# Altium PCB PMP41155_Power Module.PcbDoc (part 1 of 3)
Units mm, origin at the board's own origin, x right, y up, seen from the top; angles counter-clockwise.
Board outline 40.5 x 74.05 mm, 8 copper layers (Top Layer, Layer 1, Layer 2, Layer 3, Layer 4, Layer 5, Layer 6, Bottom Layer), stack 1.58 mm thick; 130 components, 51 nets, 407 pads, 560 vias.
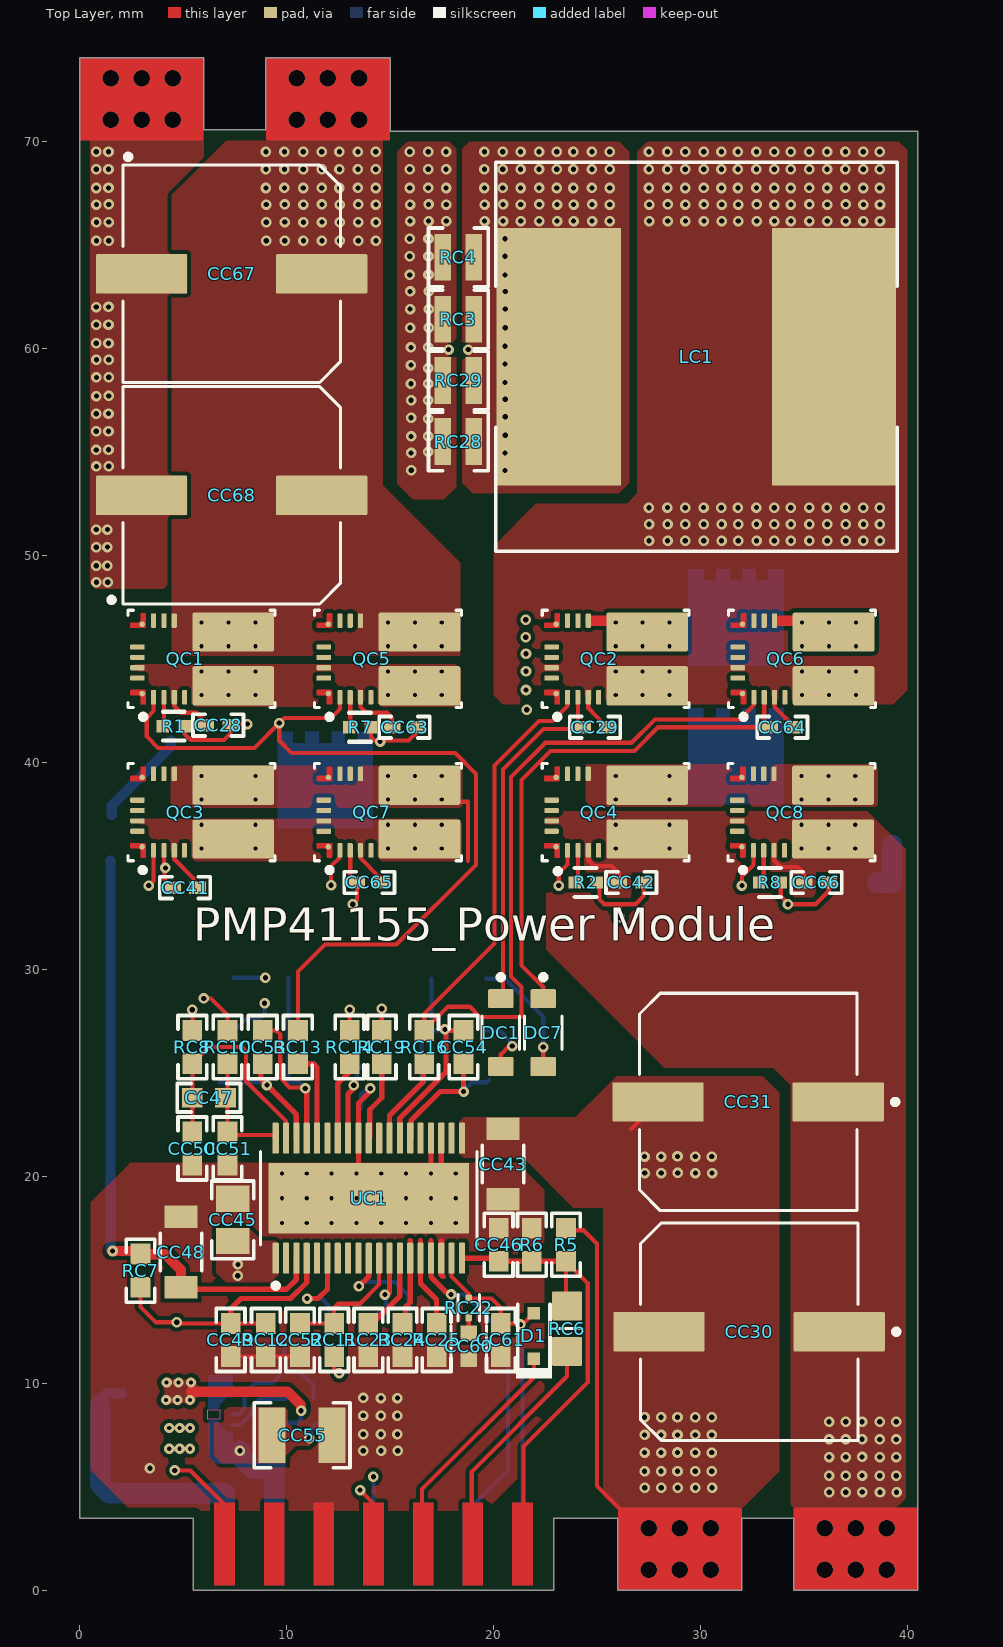
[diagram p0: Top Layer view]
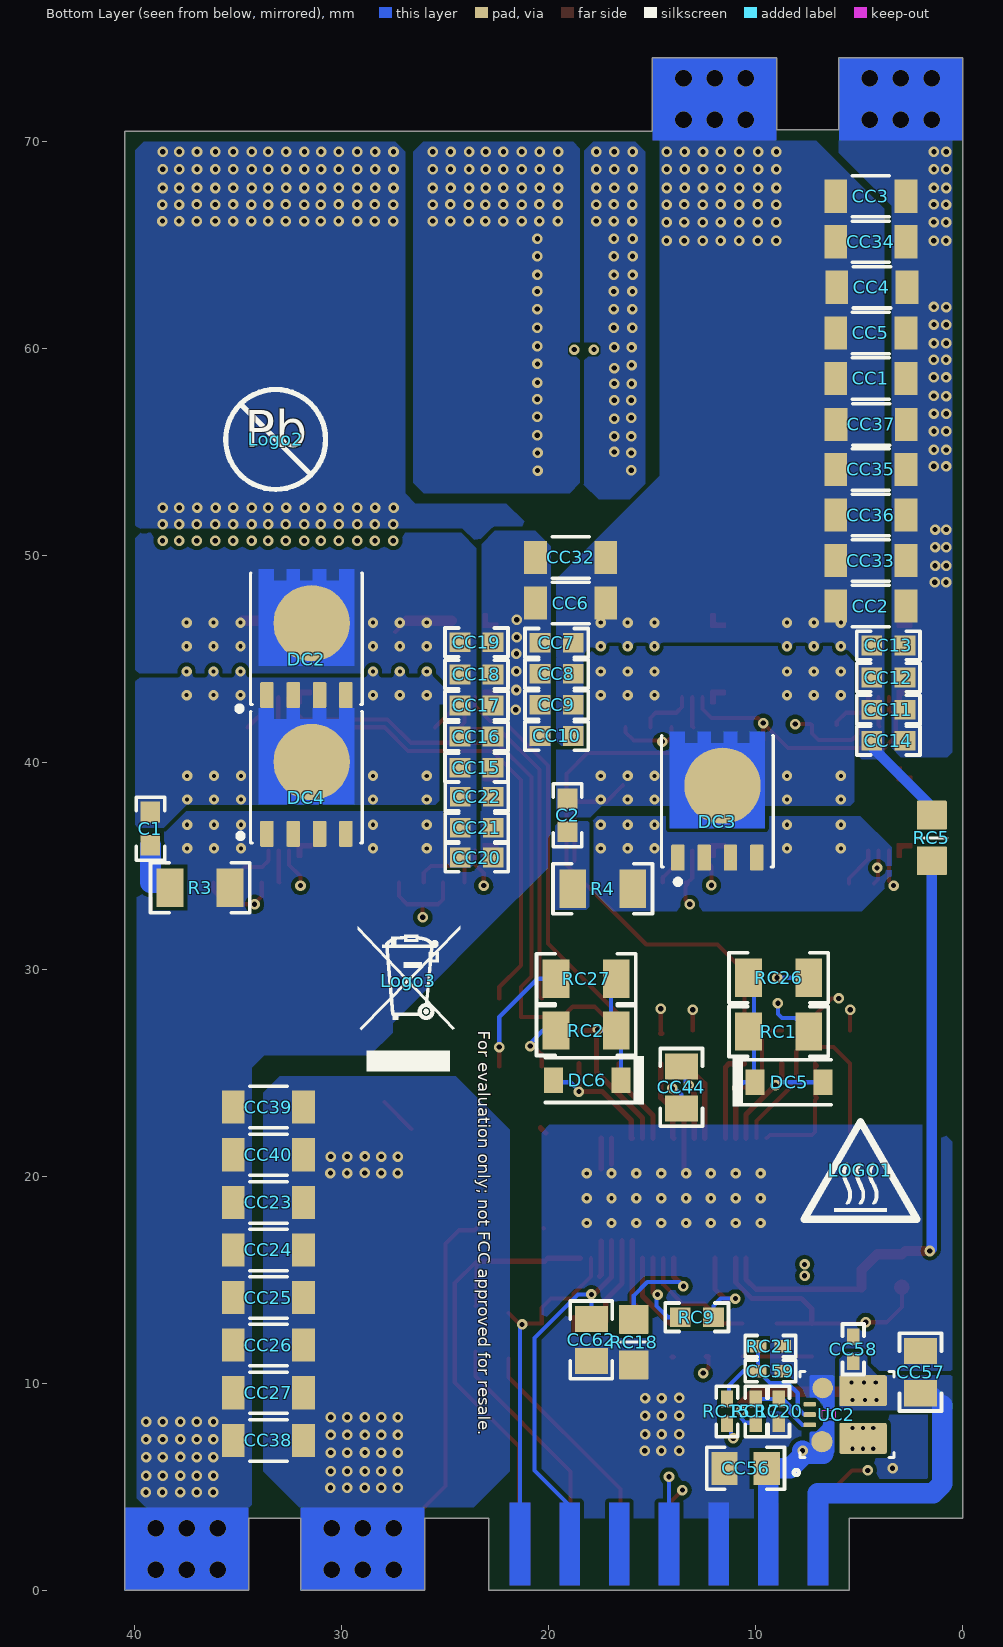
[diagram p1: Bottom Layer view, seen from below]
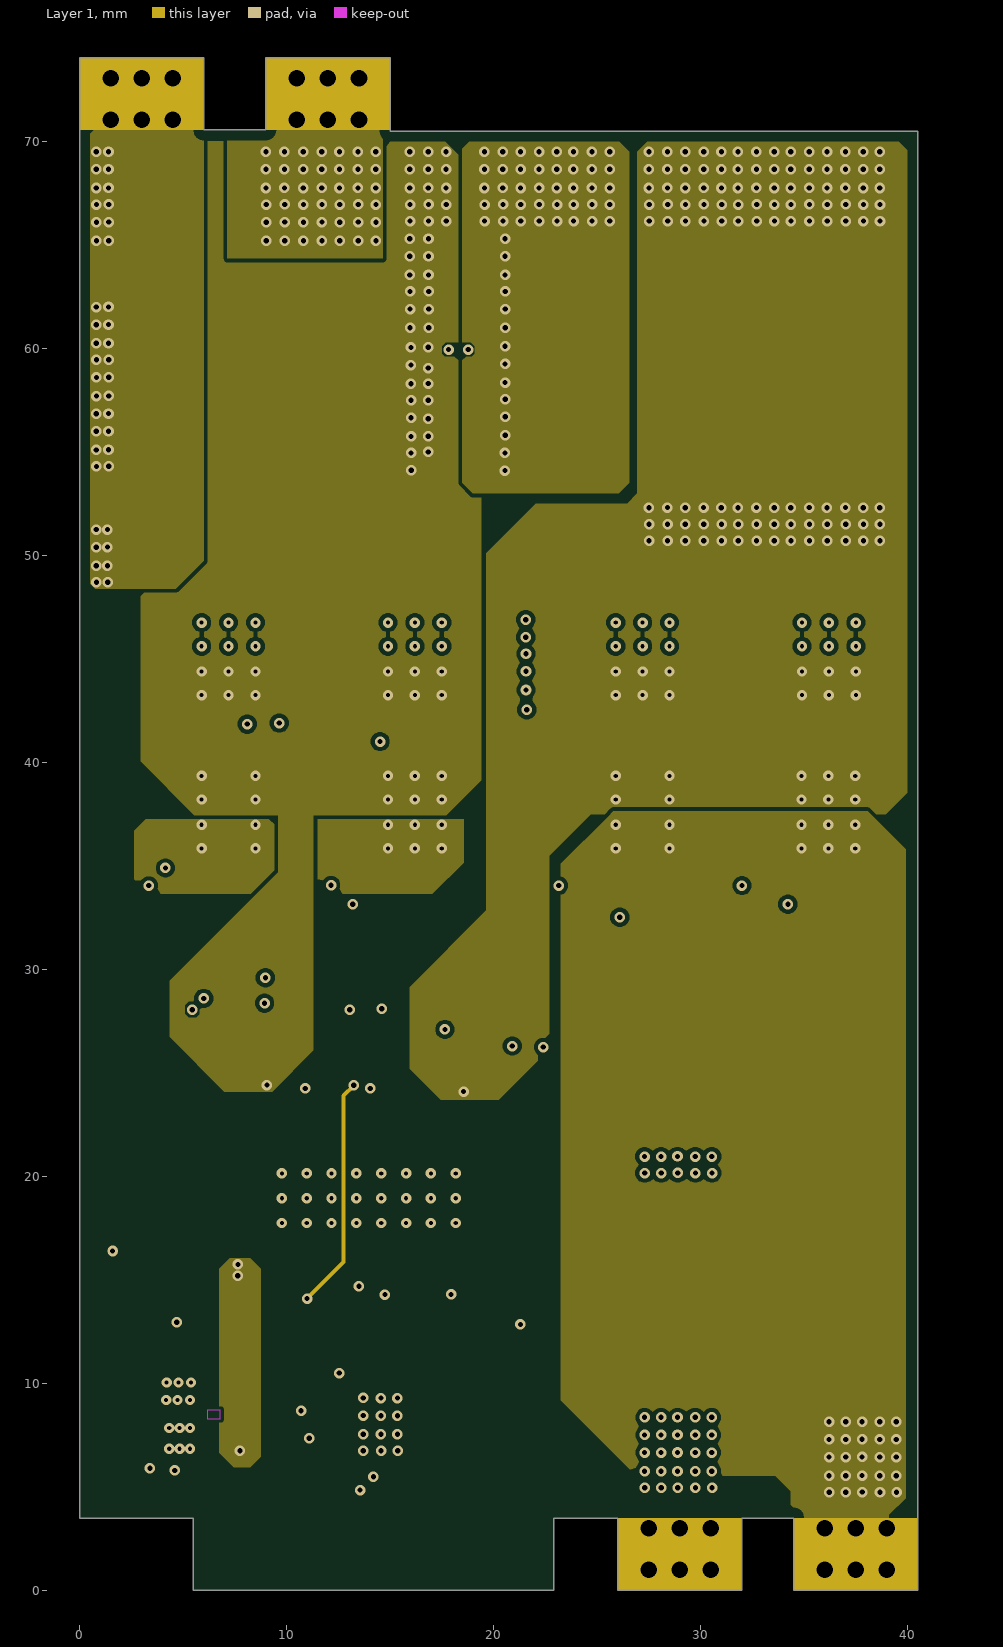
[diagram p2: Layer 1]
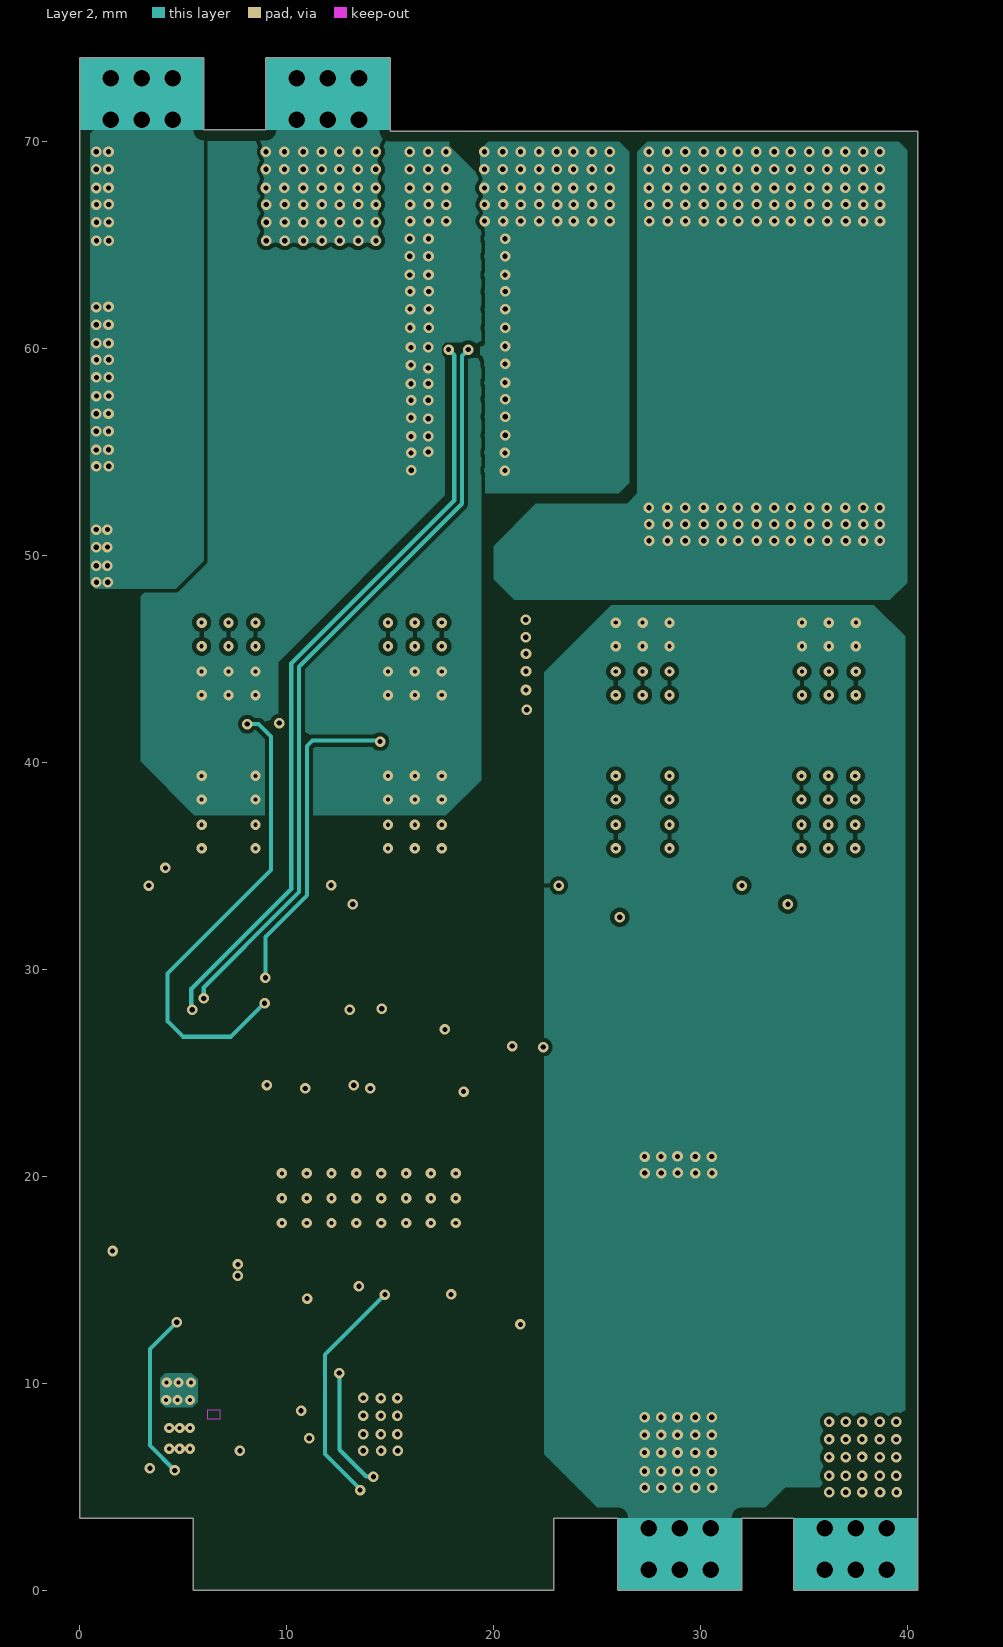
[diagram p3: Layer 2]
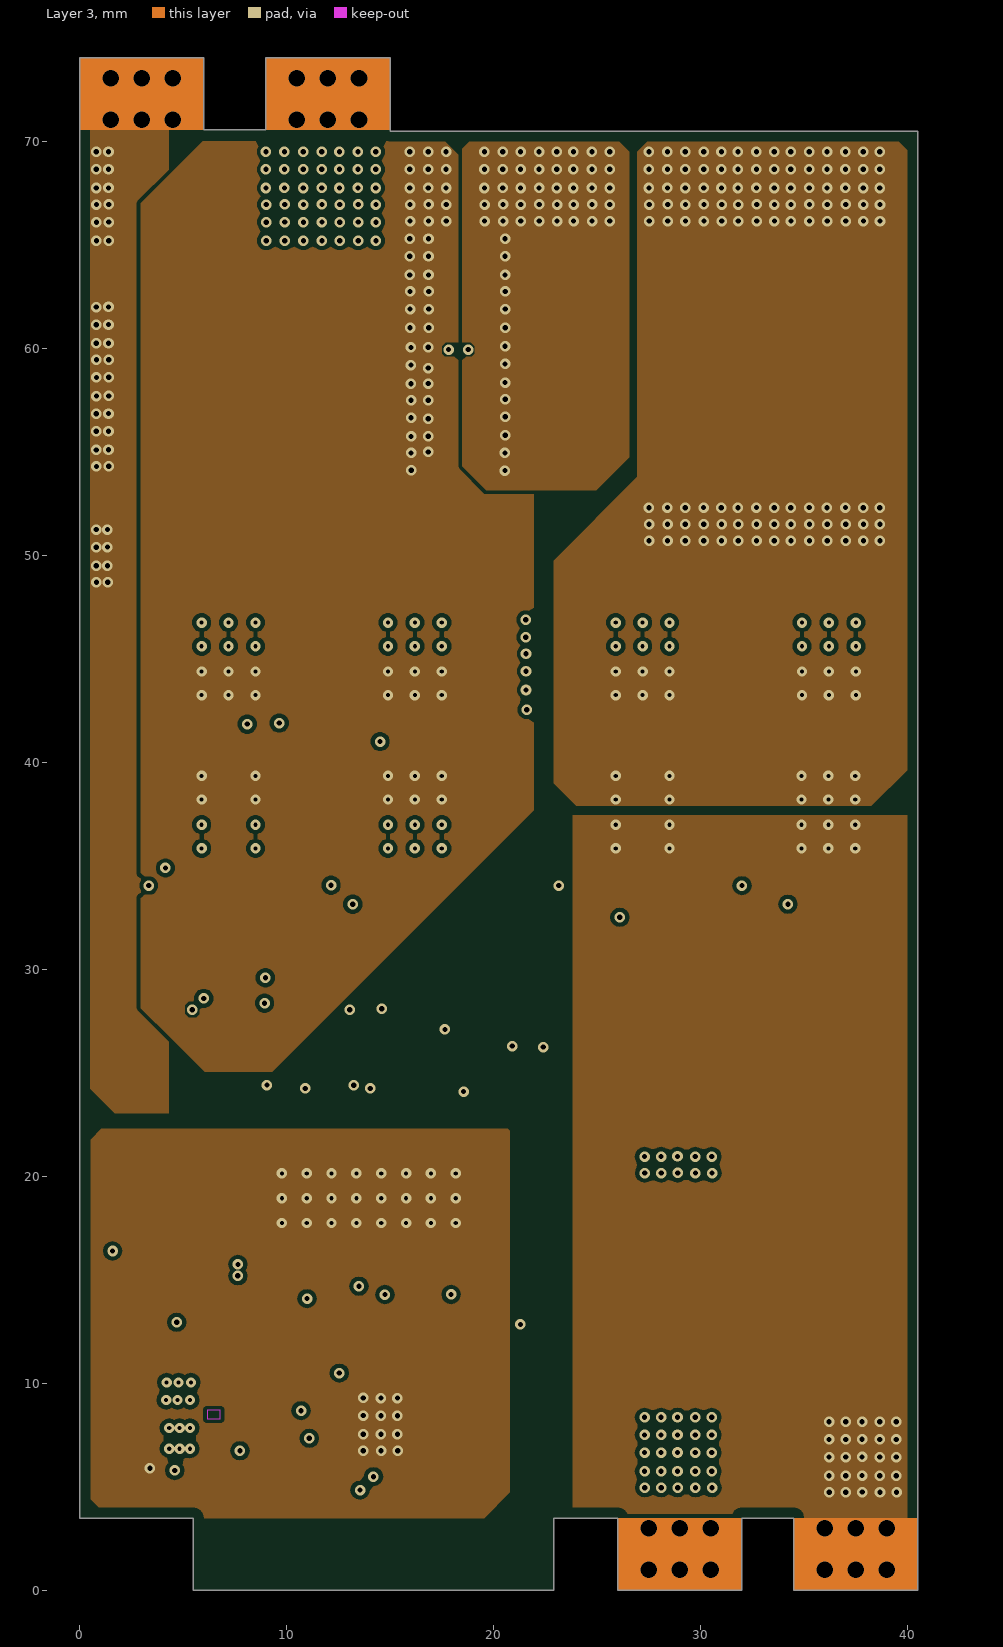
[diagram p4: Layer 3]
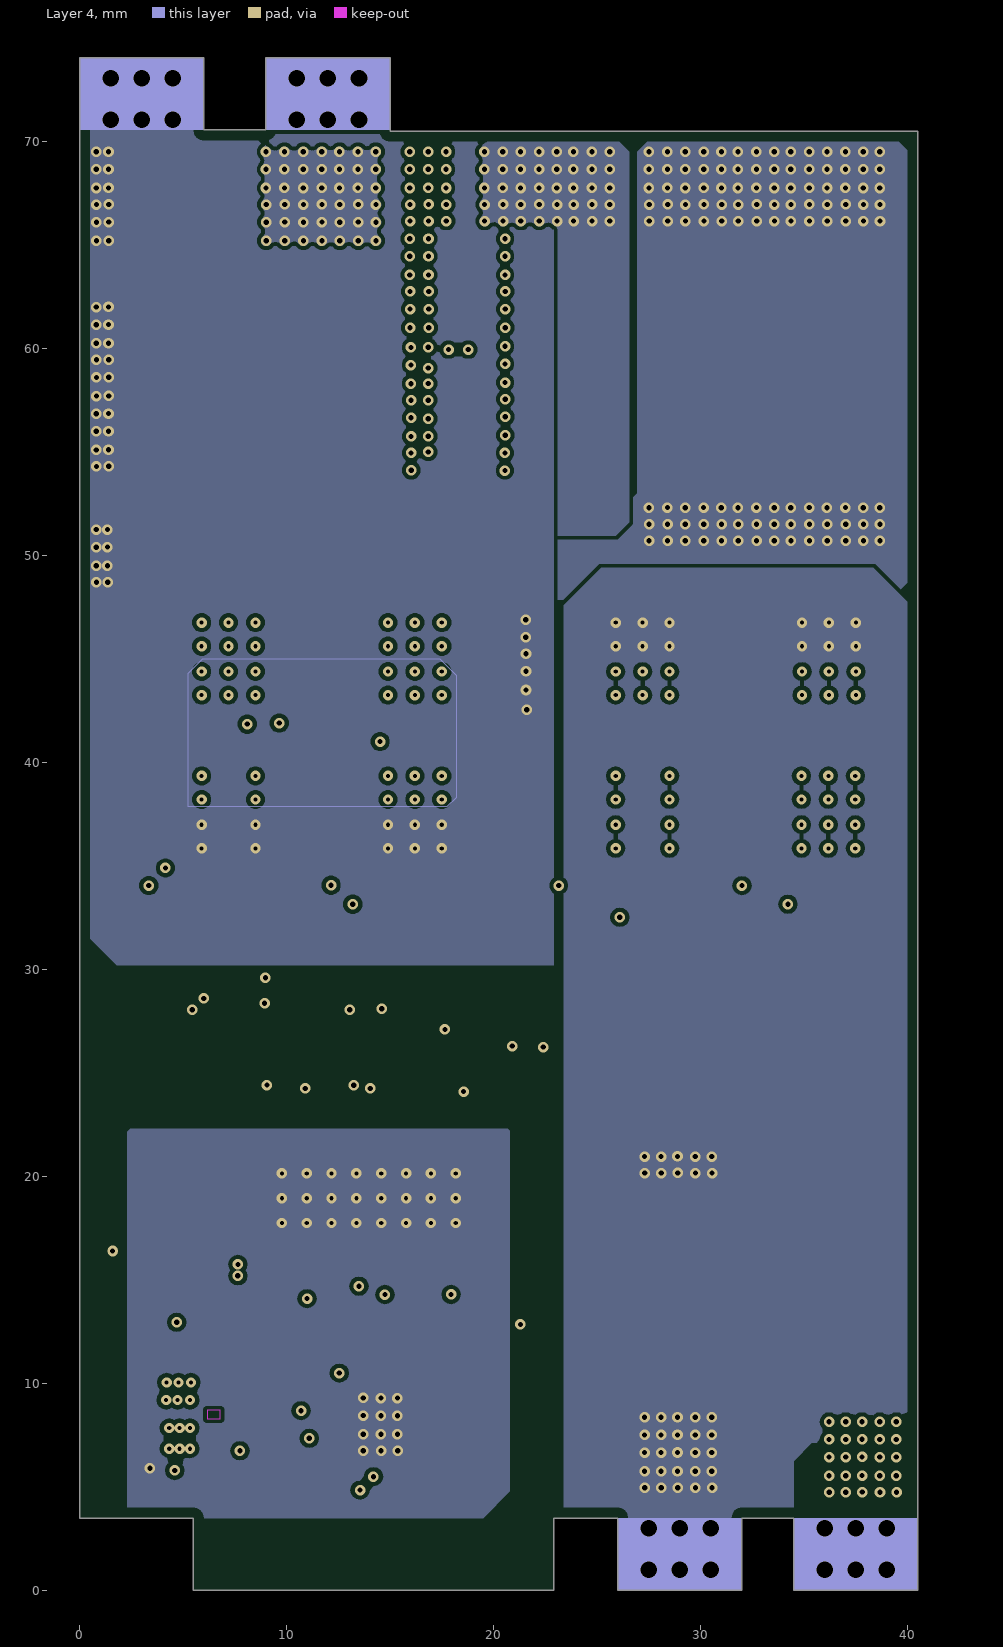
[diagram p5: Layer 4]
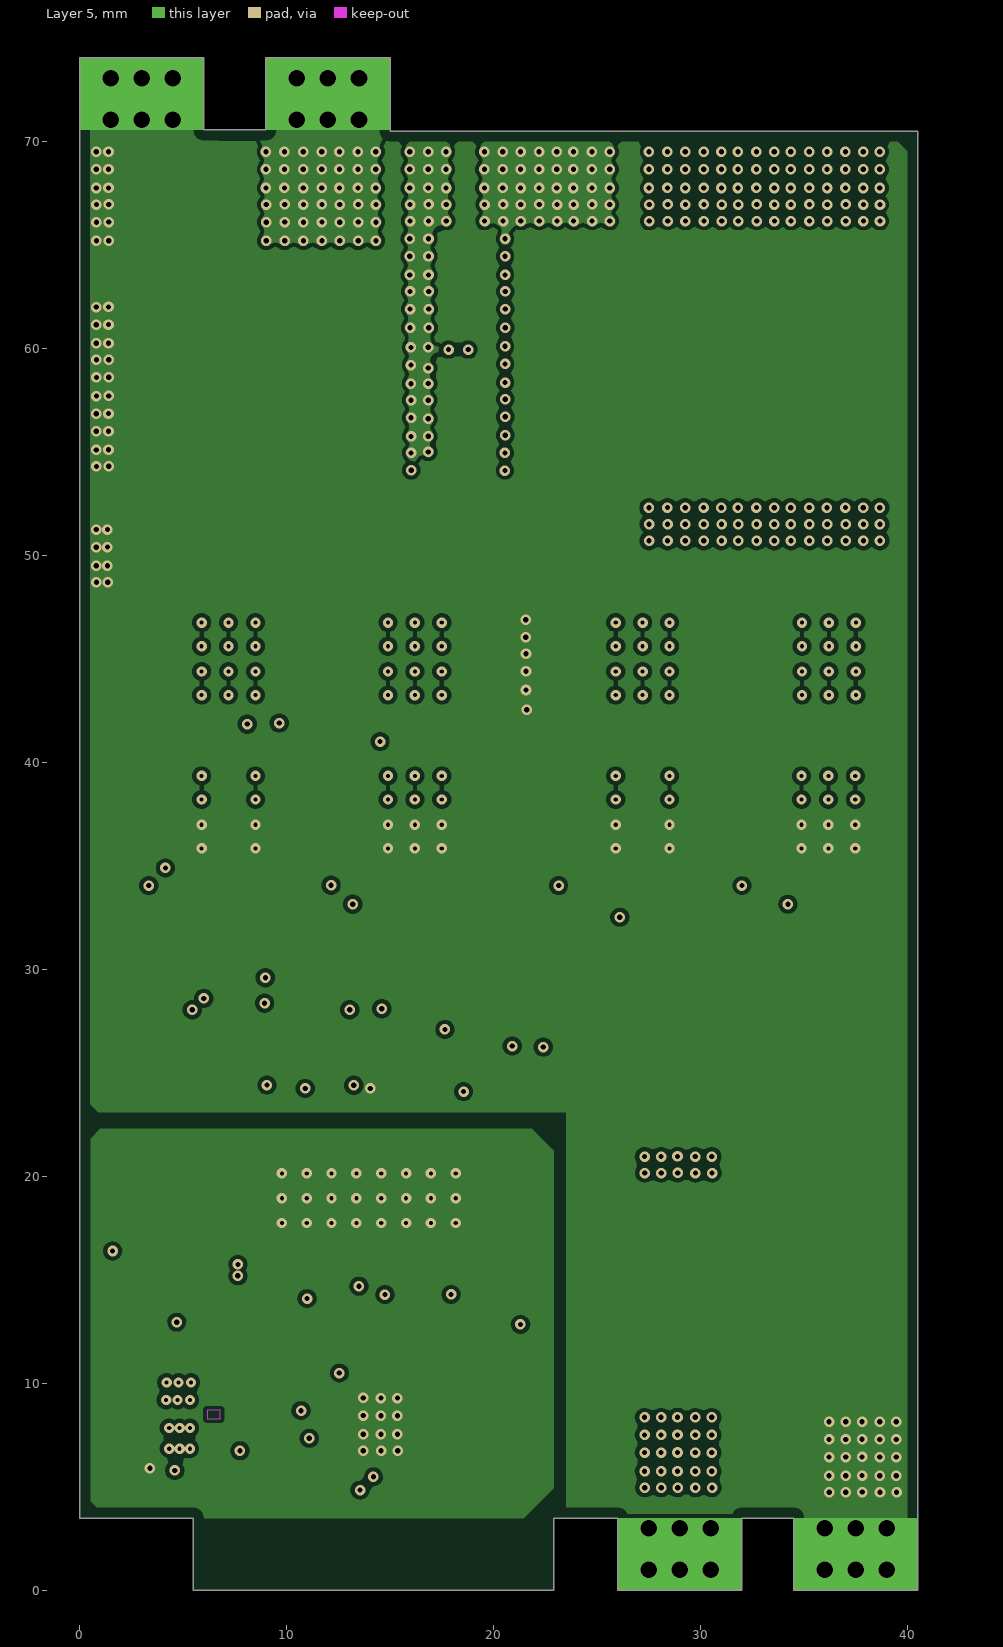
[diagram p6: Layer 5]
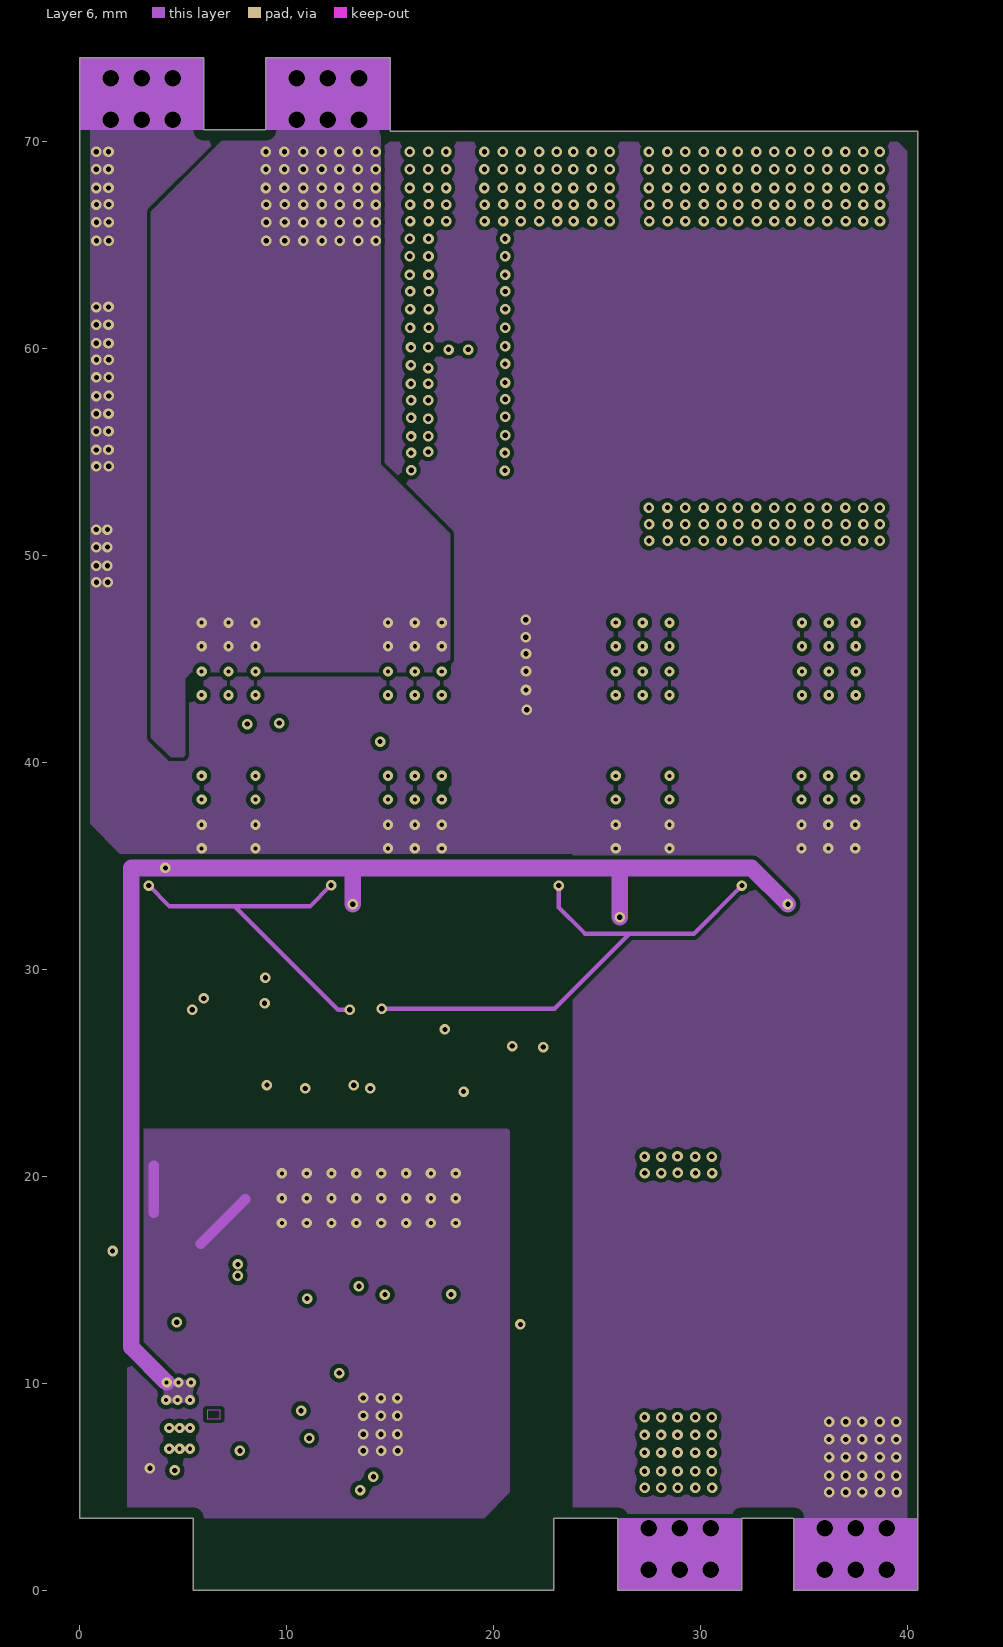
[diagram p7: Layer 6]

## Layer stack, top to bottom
Top Solder: solder mask 0.01, Solder Resist, Dk 3.5
Top Layer: signal copper 0.07
Dielectric 1: prepreg 0.26, FR-4, Dk 4.1
Layer 1: signal copper 0.07
Dielectric 2: core 0.1, FR-4, Dk 4.1
Layer 2: signal copper 0.07
Dielectric 3: core 0.1, FR-4, Dk 4.2
Layer 3: signal copper 0.07
Dielectric 4: core 0.1, FR-4, Dk 4.2
Layer 4: signal copper 0.07
Dielectric 5: core 0.1, FR-4, Dk 4.2
Layer 5: signal copper 0.07
Dielectric6: core 0.1, FR-4, Dk 4.6
Layer 6: signal copper 0.07
Dielectric 7: prepreg 0.26, FR-4, Dk 4.2
Bottom Layer: signal copper 0.07
Bottom Solder: solder mask 0.01, Solder Resist, Dk 3.5

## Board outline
5.5,0 5.5,3.5 0,3.5 0,74.05 6,74.05 6,70.55 9,70.55 9,74.05 15,74.05 15,70.5 40.5,70.5 40.5,0 34.5,0 34.5,3.5 32,3.5 32,0 26,0 26,3.5 22.9,3.5 22.9,0

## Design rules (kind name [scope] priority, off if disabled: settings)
AcuteAngle [All] p1: minimum=4.50000000000000E+0001 checktracksonly=FALSE
AssemblyTestPointUsage [All] p1: valid=2
BoardOutlineClearance BoardOutlineClearance_MountingHoles [OnCopper and InComponentClass('Mounting Holes')] p1: gap=1.016 ignorepadtopadclearanceinfootprint=FALSE
BoardOutlineClearance BoardOutlineClearance_Poly [OnCopper and IsPoly] p2: gap=0.508 ignorepadtopadclearanceinfootprint=FALSE
BoardOutlineClearance [OnCopper and Not InComponentClass('Logo') and not InComponentClass('FiducialMark') and not InRegion(1000,500,4000,800) and not InPoly] p3: gap=0.254 ignorepadtopadclearanceinfootprint=FALSE
Clearance Clearance_1 [InNetClass('HV') vs Not InNetClass('HV')] p1: gap=0.508 ignorepadtopadclearanceinfootprint=FALSE
Clearance Clearance_Keepouts [((IsTrack Or IsArc) And Not InPoly) And IsFree and IsKeepOut vs ((IsTrack Or IsArc) And Not InPoly) And IsFree and IsKeepOut] p2: gap=0 ignorepadtopadclearanceinfootprint=FALSE
Clearance Clearance_Poly [InPolygon] p3: gap=0.2 ignorepadtopadclearanceinfootprint=FALSE
Clearance Clearance_FiducialMark [IsKeepOut and InComponentClass('FiducialMark') vs IsPad and InComponentClass('FiducialMark')] p4: gap=0 ignorepadtopadclearanceinfootprint=FALSE
Clearance [All] p5: gap=0.178 ignorepadtopadclearanceinfootprint=FALSE except(0.1: Via-Via Via-Fill Via-Poly Via-Region Via-Text Via-Hole)
ComponentClearance ComponentClearance_MountingHoles_FiducialMarks [InComponentClass('Mounting Holes') vs InComponentClass('FiducialMark')] p1: gap=1.27 collisioncheckmode=3 verticalgap=0.254 showdistances=FALSE
ComponentClearance ComponentClearance_Shunt [InComponentClass('Header') vs InComponentClass('Shunt')] p2: gap=0 collisioncheckmode=3 verticalgap=0 showdistances=FALSE
ComponentClearance ComponentClearance_Logo [InComponentClass('Logo')] p3: gap=1.27 collisioncheckmode=3 verticalgap=0.254 showdistances=FALSE
ComponentClearance ComponentClearance_ScrewToNut [(HasFootprint('NY PMS 440 0025 PH')) vs (HasFootprint('Keystone_1902C'))] p4: gap=0.127 collisioncheckmode=3 verticalgap=0.254 showdistances=FALSE
ComponentClearance ComponentClearance_MountingHoles [InComponentClass('Mounting Holes')] p5: gap=6.35 collisioncheckmode=3 verticalgap=2540 showdistances=FALSE
ComponentClearance ComponentClearance_SmallPassives [HasFootprint('0201*') or HasFootprint('0402*') or HasFootprint('0508') or HasFootprint('0603*') or HasFootprint('0612') or HasFootprint('0805*') or HasFootprint('0815*') or HasFootprint('0830*') or HasFootprint('1206*') or HasFootprint('1210*') or HasFootprint('1808*') or HasFootprint('1812*') or HasFootprint('1825*') or HasFootprint('2010*') or HasFootprint('2220*') or HasFootprint('2225*') or HasFootprint('2512*') or HasFootprint('2728*') or HasFootprint('3518*') vs HasFootprint('0201*') or HasFootprint('0402*') or HasFootprint('0508') or HasFootprint('0603*') or HasFootprint('0612') or HasFootprint('0805*') or HasFootprint('0815*') or HasFootprint('0830*') or HasFootprint('1206*') or HasFootprint('1210*') or HasFootprint('1808*') or HasFootprint('1812*') or HasFootprint('1825*') or HasFootprint('2010*') or HasFootprint('2220*') or HasFootprint('2225*') or HasFootprint('2512*') or HasFootprint('2728*') or HasFootprint('3518*')] p6: gap=0.254 collisioncheckmode=3 verticalgap=0.254 showdistances=FALSE
ComponentClearance ComponentClearance_THtoSMT [IsThruComponent vs IsSMTComponent] p7: gap=1.016 collisioncheckmode=3 verticalgap=0.762 showdistances=FALSE
ComponentClearance ComponentClearance_THtoTH [IsThruComponent vs IsThruComponent] p8: gap=0.508 collisioncheckmode=3 verticalgap=0.508 showdistances=FALSE
ComponentClearance [All] p9: gap=0.254 collisioncheckmode=3 verticalgap=0.254 showdistances=FALSE
DiffPairsRouting [All] p1: maxlimit=2.54 minlimit=0.254 mostfreqgap=0.254 toplayer_minwidth=0.381 toplayer_maxwidth=0.381 toplayer_prefwidth=0.381 midlayer1_minwidth=0.381 midlayer1_maxwidth=0.381 midlayer1_prefwidth=0.381 midlayer2_minwidth=0.381 midlayer2_maxwidth=0.381 midlayer2_prefwidth=0.381 midlayer3_minwidth=0.381 midlayer3_maxwidth=0.381 midlayer3_prefwidth=0.381 midlayer4_minwidth=0.381 midlayer4_maxwidth=0.381 midlayer4_prefwidth=0.381 midlayer5_minwidth=0.381 midlayer5_maxwidth=0.381 midlayer5_prefwidth=0.381 midlayer6_minwidth=0.381 midlayer6_maxwidth=0.381 midlayer6_prefwidth=0.381 bottomlayer_minwidth=0.381 bottomlayer_maxwidth=0.381 bottomlayer_prefwidth=0.381 maxuncoupledlength=25.4
FabricationTestPointUsage TestPointUsage [All] p1: valid=2 allowmultiple=FALSE
FabricationTestpoint Testpoint [All] p1: side=3 testpointundercomponent=TRUE minsize=1.016 maxsize=2.54 preferedsize=1.524 minholesize=0 maxholesize=1.016 preferedholesize=0.813 testpointgrid=0.025 allowsidetop=TRUE allowsidebottom=TRUE usegrid=TRUE gridtolerance=0
FanoutControl Fanout_LCC [IsLCC] p1: bgadir=Out bgaviamode=Centered fanoutstyle=Auto fanoutdirection=Alternating viagrid=0.025 // Fanout_LCC (Default Rule)
FanoutControl Fanout_BGA [IsBGA] p2: bgadir=Out bgaviamode=Centered fanoutstyle=Auto fanoutdirection=Alternating viagrid=0.025 // Fanout_BGA (Default Rule)
FanoutControl Fanout_Default [All] p4: bgadir=Out bgaviamode=Centered fanoutstyle=Auto fanoutdirection=Alternating viagrid=0.025 // Fanout_Default (Default Rule)
FanoutControl Fanout_Small [(CompPinCount < 5)] p5: bgadir=Out bgaviamode=Centered fanoutstyle=Auto fanoutdirection=OutThenIn viagrid=0.025 // Fanout_Small (Default Rule)
HoleSize [All] p1: absolutevalues=TRUE maxlimit=6.375 minlimit=0.2 maxpercent=80.000 minpercent=20.000
MinimumAnnularRing MinimumAnnularRing_ThermalPadVias [IsVia and InAnyComponent] p1: minimumring=0.15
MinimumAnnularRing [All] p2: minimumring=0.127
MinimumSolderMaskSliver MinimumSolderMaskSliver_Logo [InComponentClass('Logo') vs InComponentClass('Logo')] p1: minsoldermaskwidth=0.018
MinimumSolderMaskSliver [All] p2: minsoldermaskwidth=0.1
PlaneConnect [All] p1: planeconnectstyle=Direct reliefexpansion=0.254 reliefentries=4 reliefconductorwidth=0.254 reliefairgap=0.254
PolygonConnect PolygonConnect_19 [All vs IsNamedPolygon('SGND') Or  IsNamedPolygon('SGND') Or  IsNamedPolygon('SGND') Or  IsNamedPolygon('SW2') Or  IsNamedPolygon('VBAT_DISCH_IN') Or  IsNamedPolygon('VBAT_DISCH_IN') Or  IsNamedPolygon('VBAT_DISCH_IN') Or  IsNamedPolygon('CSB_DISCH') Or  IsNamedPolygon('SGND') Or  IsNamedPolygon('no net') Or  IsNamedPolygon('SGND') Or  IsNamedPolygon('SNGD') Or  IsNamedPolygon('SGND') Or  IsNamedPolygon('SGND') Or  IsNamedPolygon('SW2') Or  IsNamedPolygon('SGND') Or  IsNamedPolygon('SGND') Or  IsNamedPolygon('CSA_DISCH') Or  IsNamedPolygon('48V_DISCH_OUT') Or  IsNamedPolygon('VBAT_DISCH_IN') Or  IsNamedPolygon('SGND') Or  IsNamedPolygon('SGND') Or  IsNamedPolygon('48V_DISCH_OUT') Or  IsNamedPolygon('SGND') Or  IsNamedPolygon('CSA_DISCH') Or  IsNamedPolygon('no net') Or  IsNamedPolygon('SGND') Or  IsNamedPolygon('SGND') Or  IsNamedPolygon('48V_DISCH_OUT') Or  IsNamedPolygon('48V_DISCH_OUT') Or  IsNamedPolygon('SGND') Or  IsNamedPolygon('12V_AUX') Or  IsNamedPolygon('48V_DISCH_OUT') Or  IsNamedPolygon('VBAT_DISCH_IN') Or  IsNamedPolygon('VBAT_DISCH_IN') Or  IsNamedPolygon('SGND')] p1: connectstyle=Direct reliefconductorwidth=0.254 reliefentries=4 polygonreliefangle="90 Angle" airgapwidth=0.254
PolygonConnect PolygonConnect_18 [All vs IsNamedPolygon('SW2') Or  IsNamedPolygon('VBAT_DISCH_IN') Or  IsNamedPolygon('VBAT_DISCH_IN') Or  IsNamedPolygon('VBAT_DISCH_IN') Or  IsNamedPolygon('48V_DISCH_OUT') Or  IsNamedPolygon('VBAT_DISCH_IN') Or  IsNamedPolygon('SGND') Or  IsNamedPolygon('SGND') Or  IsNamedPolygon('SGND') Or  IsNamedPolygon('SGND') Or  IsNamedPolygon('SGND') Or  IsNamedPolygon('VBAT_DISCH_IN') Or  IsNamedPolygon('SGND') Or  IsNamedPolygon('CSA_DISCH') Or  IsNamedPolygon('SGND') Or  IsNamedPolygon('48V_DISCH_OUT') Or  IsNamedPolygon('48V_DISCH_OUT') Or  IsNamedPolygon('no net') Or  IsNamedPolygon('SGND') Or  IsNamedPolygon('SGND') Or  IsNamedPolygon('SGND') Or  IsNamedPolygon('SGND') Or  IsNamedPolygon('12V_AUX') Or  IsNamedPolygon('CSA_DISCH') Or  IsNamedPolygon('CSB_DISCH') Or  IsNamedPolygon('SGND') Or  IsNamedPolygon('SGND') Or  IsNamedPolygon('VBAT_DISCH_IN')] p2: connectstyle=Direct reliefconductorwidth=0.254 reliefentries=4 polygonreliefangle="90 Angle" airgapwidth=0.254
PolygonConnect PolygonConnect_17 [All vs IsNamedPolygon('SGND') Or  IsNamedPolygon('VBAT_DISCH_IN') Or  IsNamedPolygon('SGND') Or  IsNamedPolygon('VBAT_DISCH_IN') Or  IsNamedPolygon('CSA_DISCH') Or  IsNamedPolygon('VBAT_DISCH_IN') Or  IsNamedPolygon('VBAT_DISCH_IN') Or  IsNamedPolygon('SGND') Or  IsNamedPolygon('SGND') Or  IsNamedPolygon('48V_DISCH_OUT') Or  IsNamedPolygon('CSA_DISCH') Or  IsNamedPolygon('SGND') Or  IsNamedPolygon('VBAT_DISCH_IN') Or  IsNamedPolygon('SGND') Or  IsNamedPolygon('no net') Or  IsNamedPolygon('48V_DISCH_OUT') Or  IsNamedPolygon('SGND') Or  IsNamedPolygon('CSB_DISCH') Or  IsNamedPolygon('SW2') Or  IsNamedPolygon('SGND') Or  IsNamedPolygon('48V_DISCH_OUT') Or  IsNamedPolygon('SGND') Or  IsNamedPolygon('VBAT_DISCH_IN')] p3: connectstyle=Direct reliefconductorwidth=0.254 reliefentries=4 polygonreliefangle="90 Angle" airgapwidth=0.254
PolygonConnect PolygonConnect_16 [All vs IsNamedPolygon('SGND') Or  IsNamedPolygon('SGND') Or  IsNamedPolygon('CSA_DISCH') Or  IsNamedPolygon('48V_DISCH_OUT') Or  IsNamedPolygon('VBAT_DISCH_IN') Or  IsNamedPolygon('SGND') Or  IsNamedPolygon('SGND') Or  IsNamedPolygon('SGND') Or  IsNamedPolygon('SGND') Or  IsNamedPolygon('VBAT_DISCH_IN') Or  IsNamedPolygon('VBAT_DISCH_IN') Or  IsNamedPolygon('CSB_DISCH') Or  IsNamedPolygon('SGND') Or  IsNamedPolygon('VBAT_DISCH_IN') Or  IsNamedPolygon('VBAT_DISCH_IN') Or  IsNamedPolygon('SGND') Or  IsNamedPolygon('VBAT_DISCH_IN') Or  IsNamedPolygon('SW2') Or  IsNamedPolygon('CSA_DISCH') Or  IsNamedPolygon('SGND')] p4: connectstyle=Direct reliefconductorwidth=0.254 reliefentries=4 polygonreliefangle="90 Angle" airgapwidth=0.254
PolygonConnect PolygonConnect_15 [All vs IsNamedPolygon('CSA_DISCH') Or  IsNamedPolygon('SGND') Or  IsNamedPolygon('SGND') Or  IsNamedPolygon('48V_DISCH_OUT') Or  IsNamedPolygon('VBAT_DISCH_IN') Or  IsNamedPolygon('SW2') Or  IsNamedPolygon('VBAT_DISCH_IN') Or  IsNamedPolygon('SGND') Or  IsNamedPolygon('VBAT_DISCH_IN') Or  IsNamedPolygon('CSB_DISCH') Or  IsNamedPolygon('VBAT_DISCH_IN') Or  IsNamedPolygon('CSA_DISCH') Or  IsNamedPolygon('VBAT_DISCH_IN')] p5: connectstyle=Direct reliefconductorwidth=0.254 reliefentries=4 polygonreliefangle="90 Angle" airgapwidth=0.254
PolygonConnect PolygonConnect_14 [All vs IsNamedPolygon('SW2') Or  IsNamedPolygon('48V_DISCH_OUT') Or  IsNamedPolygon('SGND') Or  IsNamedPolygon('SGND') Or  IsNamedPolygon('CSA_DISCH') Or  IsNamedPolygon('CSB_DISCH')] p6: connectstyle=Direct reliefconductorwidth=0.254 reliefentries=4 polygonreliefangle="90 Angle" airgapwidth=0.254
PolygonConnect PolygonConnect_13 [All vs IsNamedPolygon('SGND') Or  IsNamedPolygon('48V_DISCH_OUT') Or  IsNamedPolygon('SGND') Or  IsNamedPolygon('CSB_DISCH') Or  IsNamedPolygon('CSA_DISCH')] p7: connectstyle=Direct reliefconductorwidth=0.254 reliefentries=4 polygonreliefangle="90 Angle" airgapwidth=0.254
PolygonConnect PolygonConnect_12 [All vs IsNamedPolygon('48V_DISCH_OUT') Or  IsNamedPolygon('SGND') Or  IsNamedPolygon('SGND')] p8: connectstyle=Direct reliefconductorwidth=0.254 reliefentries=4 polygonreliefangle="90 Angle" airgapwidth=0.254
PolygonConnect PolygonConnect_11 [All vs IsNamedPolygon('GND') Or  IsNamedPolygon('D101_2') Or  IsNamedPolygon('V+') Or  IsNamedPolygon('GND') Or  IsNamedPolygon('C128_1') Or  IsNamedPolygon('J2_2') Or  IsNamedPolygon('CS') Or  IsNamedPolygon('V+') Or  IsNamedPolygon('GND') Or  IsNamedPolygon('J2_2') Or  IsNamedPolygon('PGND') Or  IsNamedPolygon('12V') Or  IsNamedPolygon('PGND') Or  IsNamedPolygon('PGND') Or  IsNamedPolygon('V+') Or  IsNamedPolygon('V+') Or  IsNamedPolygon('D101_2') Or  IsNamedPolygon('CS') Or  IsNamedPolygon('GND')] p9: connectstyle=Direct reliefconductorwidth=0.254 reliefentries=4 polygonreliefangle="90 Angle" airgapwidth=0.254
PolygonConnect PolygonConnect_10 [All vs IsNamedPolygon('GND') Or  IsNamedPolygon('C128_1') Or  IsNamedPolygon('GND') Or  IsNamedPolygon('J2_2') Or  IsNamedPolygon('GND') Or  IsNamedPolygon('D101_2') Or  IsNamedPolygon('J2_2') Or  IsNamedPolygon('V+') Or  IsNamedPolygon('PGND') Or  IsNamedPolygon('CS') Or  IsNamedPolygon('V+')] p10: connectstyle=Direct reliefconductorwidth=0.254 reliefentries=4 polygonreliefangle="90 Angle" airgapwidth=0.254
PolygonConnect PolygonConnect_9 [All vs IsNamedPolygon('J2_2') Or  IsNamedPolygon('GND') Or  IsNamedPolygon('8V5') Or  IsNamedPolygon('V+') Or  IsNamedPolygon('R117_1') Or  IsNamedPolygon('PGND') Or  IsNamedPolygon('PGND') Or  IsNamedPolygon('Drv') Or  IsNamedPolygon('V+') Or  IsNamedPolygon('V+') Or  IsNamedPolygon('C128_1') Or  IsNamedPolygon('GND') Or  IsNamedPolygon('GND') Or  IsNamedPolygon('J2_2') Or  IsNamedPolygon('PGND')] p11: connectstyle=Direct reliefconductorwidth=0.254 reliefentries=4 polygonreliefangle="90 Angle" airgapwidth=0.254
PolygonConnect PolygonConnect_8 [All vs IsNamedPolygon('8V5') Or  IsNamedPolygon('J2_2') Or  IsNamedPolygon('PGND') Or  IsNamedPolygon('GND') Or  IsNamedPolygon('GND') Or  IsNamedPolygon('V+') Or  IsNamedPolygon('J2_2') Or  IsNamedPolygon('V+') Or  IsNamedPolygon('C128_1') Or  IsNamedPolygon('V+') Or  IsNamedPolygon('PGND') Or  IsNamedPolygon('J2_2') Or  IsNamedPolygon('J2_2') Or  IsNamedPolygon('R117_1')] p12: connectstyle=Direct reliefconductorwidth=0.254 reliefentries=4 polygonreliefangle="90 Angle" airgapwidth=0.254
PolygonConnect PolygonConnect_7 [All vs IsNamedPolygon('J2_2') Or  IsNamedPolygon('J2_2') Or  IsNamedPolygon('J2_2') Or  IsNamedPolygon('C128_1') Or  IsNamedPolygon('J2_2')] p13: connectstyle=Direct reliefconductorwidth=0.254 reliefentries=4 polygonreliefangle="90 Angle" airgapwidth=0.254
PolygonConnect PolygonConnect_6 [All vs IsNamedPolygon('J2_2')] p14: connectstyle=Direct reliefconductorwidth=0.254 reliefentries=4 polygonreliefangle="90 Angle" airgapwidth=0.254
PolygonConnect PolygonConnect_5 [All vs IsNamedPolygon('GND') Or  IsNamedPolygon('Vout') Or  IsNamedPolygon('Bottom Layer-SW') Or  IsNamedPolygon('GND') Or  IsNamedPolygon('C1_1') Or  IsNamedPolygon('Q1_3') Or  IsNamedPolygon('J2_2') Or  IsNamedPolygon('GND') Or  IsNamedPolygon('J2_2') Or  IsNamedPolygon('GND') Or  IsNamedPolygon('Vout') Or  IsNamedPolygon('Top Layer-SW') Or  IsNamedPolygon('Q1_3') Or  IsNamedPolygon('GND') Or  IsNamedPolygon('J2_2') Or  IsNamedPolygon('J2_2') Or  IsNamedPolygon('GND') Or  IsNamedPolygon('GND') Or  IsNamedPolygon('GND') Or  IsNamedPolygon('GND') Or  IsNamedPolygon('GND')] p15: connectstyle=Direct reliefconductorwidth=0.254 reliefentries=4 polygonreliefangle="90 Angle" airgapwidth=0.254
PolygonConnect PolygonConnect_4 [All vs IsNamedPolygon('GND') Or  IsNamedPolygon('Bottom Layer-SW') Or  IsNamedPolygon('C1_1') Or  IsNamedPolygon('Top Layer-SW') Or  IsNamedPolygon('GND') Or  IsNamedPolygon('GND') Or  IsNamedPolygon('GND') Or  IsNamedPolygon('Q1_3') Or  IsNamedPolygon('Vout') Or  IsNamedPolygon('Q1_3') Or  IsNamedPolygon('Vout')] p16: connectstyle=Direct reliefconductorwidth=0.254 reliefentries=4 polygonreliefangle="90 Angle" airgapwidth=0.254
PolygonConnect PolygonConnect_3 [All vs IsNamedPolygon('Q1_3') Or  IsNamedPolygon('Q1_3') Or  IsNamedPolygon('Top Layer-SW') Or  IsNamedPolygon('C1_1') Or  IsNamedPolygon('Bottom Layer-SW')] p17: connectstyle=Direct reliefconductorwidth=0.254 reliefentries=4 polygonreliefangle="90 Angle" airgapwidth=0.254
PolygonConnect PolygonConnect_2 [All vs IsNamedPolygon('Top Layer-SW') Or  IsNamedPolygon('Bottom Layer-SW')] p18: connectstyle=Direct reliefconductorwidth=0.254 reliefentries=4 polygonreliefangle="90 Angle" airgapwidth=0.254
PolygonConnect PolygonConnect_1 [All vs IsNamedPolygon('Bottom Layer-SW') Or  IsNamedPolygon('Top Layer-SW')] p19: thpad.connectstyle=Direct thpad.reliefconductorwidth=0.254 thpad.reliefentries=4 thpad.polygonreliefangle="90 Angle" thpad.airgapwidth=0.254 smdpad.connectstyle=Direct smdpad.reliefconductorwidth=0.254 smdpad.reliefentries=4 smdpad.polygonreliefangle="90 Angle" smdpad.airgapwidth=0.254 via.connectstyle=Relief via.reliefconductorwidth=0.254 via.reliefentries=4 via.polygonreliefangle="90 Angle" via.airgapwidth=0.254
PolygonConnect [All] p20: connectstyle=Direct reliefconductorwidth=0.254 reliefentries=4 polygonreliefangle="90 Angle" airgapwidth=0.254
RoutingVias ThermalPadVias [IsVia and InAnyComponent] p1: holewidth=0.2 width=0.5 viastyle="Through Hole" minholewidth=0.2 minwidth=0.5 maxholewidth=0.33 maxwidth=0.6
RoutingVias [All] p2: holewidth=0.254 width=0.508 viastyle="Through Hole" minholewidth=0.2 minwidth=0.508 maxholewidth=1.016 maxwidth=1.651
SilkToBoardRegionClearance [Not ((IsComment or IsDesignator) And (Hide <> 'False')) and not InRegion(1000,500,4000,800)] p1:
SilkToSilkClearance SilkToSilkClearance_Pb-FreeLogo [(HasFootprint('Pb-Free_Overlay_Medium') OR HasFootprint('Pb-Free_Overlay_Small')) vs (HasFootprint('Pb-Free_Overlay_Medium') OR HasFootprint('Pb-Free_Overlay_Small'))] p1: silktosilkclearance=0
SilkToSilkClearance [All] p2: silktosilkclearance=0.102
SilkToSolderMaskClearance SilkToComponentPadClearance [(IsPad or IsFill or IsRegion) and InAnycomponent] p1: minsilkscreentomaskgap=0.127 clearancetoexposedcopper=TRUE
SilkToSolderMaskClearance "Silk to Solder Mask Opening" [All] p2: minsilkscreentomaskgap=0.102 clearancetoexposedcopper=FALSE
SolderMaskExpansion [All] p1: expansion=0.05 istentingtop=FALSE
SupplyNets "Schematic Supply Nets" [InNet('SGND')] p1: voltage=0.000
Width [All] p1: maxlimit=2.54 minlimit=0.152 preferedwidth=0.2 checkconnectedcopper=TRUE
15 further rules are at their usual default settings.

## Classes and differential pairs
component class "PMP41155_Power Module_1": CC63 CC64 CC65 CC66 CC541 CC571 DC7 QC5 QC6 QC7 QC8 R7 R8 RC26 RC27 RC28 RC29
component class "PMP41155_Power Module": !PCB100 C1 C2 CC1 CC2 CC3 CC4 CC5 CC6 CC7 CC8 CC9 CC10 CC11 CC12 CC13 CC14 CC15 CC16 CC17 CC18 CC19 CC20 CC21 CC22 CC23 CC24 CC25 CC26 CC27 CC28 CC29 CC30 CC31 CC32 CC33 CC34 CC35 CC36 CC37 CC38 CC39 CC40 CC41 CC42 CC43 CC44 CC45 CC46 CC47 CC48 CC49 CC50 CC51 CC52 CC53 CC54 CC55 CC56 CC57 CC58 CC59 CC60 CC61 CC62 CC67 CC68 D1 DC1 DC2 DC3 DC4 DC5 DC6 LC1 LOGO1 Logo2 Logo3 Logo4 QC1 QC2 QC3 QC4 R1 R2 R3 R4 R5 R6 RC1 RC2 RC3 RC4 RC5 RC6 RC7 RC8 RC9 RC10 RC11 RC12 RC13 RC14 RC15 RC16 RC17 RC18 RC19 RC20 RC21 RC22 RC23 RC24 RC25 UC1 UC2

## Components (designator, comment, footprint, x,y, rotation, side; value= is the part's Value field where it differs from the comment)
C1 "GRM188R72A182KA01D" 0603 39.25,36.8 r270 bottom value=1800pF
C2 "GRM188R72A182KA01D" 0603 19.1,37.45 r270 bottom value=1800pF
CC1 "GRJ31CC72A475KE01L" 1206_180 4.45,58.55 r180 bottom value=4.7uF
CC2 "GRJ31CC72A475KE01L" 1206_180 4.45,47.55 r180 bottom value=4.7uF
CC3 "GRJ31CC72A475KE01L" 1206_180 4.45,67.35 r180 bottom value=4.7uF
CC4 "GRJ31CC72A475KE01L" 1206_180 4.4,62.95 r180 bottom value=4.7uF
CC5 "GRJ31CC72A475KE01L" 1206_180 4.45,60.75 r180 bottom value=4.7uF
CC6 "GRJ31CC72A475KE01L" 1206_180 18.95,47.7 r0 bottom value=4.7uF
CC7 "CGA3E2X7R2A223K080AA" 0603 19.63,45.778 r0 bottom value=0.022uF
CC8 "CGA3E2X7R2A223K080AA" 0603 19.63,44.278 r0 bottom value=0.022uF
CC9 "CGA3E2X7R2A223K080AA" 0603 19.63,42.778 r0 bottom value=0.022uF
CC10 "CGA3E2X7R2A223K080AA" 0603 19.63,41.278 r0 bottom value=0.022uF
CC11 "CGA3E2X7R2A223K080AA" 0603 3.6,42.55 r180 bottom value=0.022uF
CC12 "CGA3E2X7R2A223K080AA" 0603 3.6,44.1 r180 bottom value=0.022uF
CC13 "CGA3E2X7R2A223K080AA" 0603 3.6,45.65 r180 bottom value=0.022uF
CC14 "CGA3E2X7R2A223K080AA" 0603 3.6,41.05 r180 bottom value=0.022uF
CC15 "CGA3E2X7R2A223K080AA" 0603 23.5,39.75 r180 bottom value=0.022uF
CC16 "CGA3E2X7R2A223K080AA" 0603 23.5,41.25 r180 bottom value=0.022uF
CC17 "CGA3E2X7R2A223K080AA" 0603 23.5,42.75 r180 bottom value=0.022uF
CC18 "CGA3E2X7R2A223K080AA" 0603 23.5,44.25 r180 bottom value=0.022uF
CC19 "CGA3E2X7R2A223K080AA" 0603 23.5,45.8 r180 bottom value=0.022uF
CC20 "CGA3E2X7R2A223K080AA" 0603 23.486,35.406 r180 bottom value=0.022uF
CC21 "CGA3E2X7R2A223K080AA" 0603 23.486,36.848 r180 bottom value=0.022uF
CC22 "CGA3E2X7R2A223K080AA" 0603 23.486,38.348 r180 bottom value=0.022uF
CC23 "GRJ31CC72A475KE01L" 1206_180 33.55,18.75 r0 bottom value=4.7uF
CC24 "GRJ31CC72A475KE01L" 1206_180 33.55,16.45 r0 bottom value=4.7uF
CC25 "GRJ31CC72A475KE01L" 1206_180 33.55,14.15 r0 bottom value=4.7uF
CC26 "GRJ31CC72A475KE01L" 1206_180 33.55,11.85 r0 bottom value=4.7uF
CC27 "GRJ31CC72A475KE01L" 1206_180 33.55,9.55 r0 bottom value=4.7uF
CC28 "GCM155R71C104JA55D" 0402 6.7,41.8 r180 top value=0.1uF
CC29 "GCM155R71C104JA55D" 0402 24.9,41.7 r0 top value=0.1uF
CC30 "865081757008" FP-865081757008_SMT_CAP_10MM3_10MM3-MFG 32.35,12.5 r180 top value=47µF
CC31 "865081757008" FP-865081757008_SMT_CAP_10MM3_10MM3-MFG 32.3,23.6 r180 top value=47µF
CC32 "GRJ31CC72A475KE01L" 1206_180 18.95,49.9 r0 bottom value=4.7uF
CC33 "GRJ31CC72A475KE01L" 1206_180 4.45,49.75 r180 bottom value=4.7uF
CC34 "GRJ31CC72A475KE01L" 1206_180 4.45,65.15 r180 bottom value=4.7uF
CC35 "GRJ31CC72A475KE01L" 1206_180 4.45,54.15 r180 bottom value=4.7uF
CC36 "GRJ31CC72A475KE01L" 1206_180 4.45,51.95 r180 bottom value=4.7uF
CC37 "GRJ31CC72A475KE01L" 1206_180 4.435,56.331 r180 bottom value=4.7uF
CC38 "GRJ31CC72A475KE01L" 1206_180 33.55,7.25 r0 bottom value=4.7uF
CC39 "GRJ31CC72A475KE01L" 1206_180 33.55,23.35 r0 bottom value=4.7uF
CC40 "GRJ31CC72A475KE01L" 1206_180 33.55,21.05 r0 bottom value=4.7uF
CC41 "GCM155R71C104JA55D" 0402 5.1,33.95 r0 top value=0.1uF
CC42 "GCM155R71C104JA55D" 0402 26.65,34.2 r180 top value=0.1uF
CC43 "GRJ31CC72A475KE01L" 1206_180 20.45,20.6 r270 top value=4.7uF
CC44 "GRM21BR61A476ME15L" 0805_HV 13.6,24.3 r270 bottom value=47uF
CC45 "GRM219R61E225KA12D" 0805_HV 7.4,17.9 r270 top value=2.2uF
CC46 "GRM188R71H221KA01D" 0603 20.25,16.7 r90 top value=220pF
CC47 "06035A680JAT2A" 0603 6.25,23.8 r0 top value=68pF
CC48 "GRJ31CC72A475KE01L" 1206_180 4.9,16.35 r90 top value=4.7uF
CC49 "GRM1885C1H102JA01D" 0603 7.3,12.1 r270 top value=1000pF
CC50 "C0603C470J5GACTU" 0603 5.45,21.35 r270 top value=47pF
CC51 "C0603C470J5GACTU" 0603 7.15,21.35 r270 top value=47pF
CC52 "GRM188R61H222KA01D" 0603 10.65,12.1 r90 top value=2200pF
CC53 "GCM188R71C104KA37J" 0603 8.85,26.25 r90 top value=0.1uF
CC54 "GCM188R71C104KA37J" 0603 18.55,26.25 r90 top value=0.1uF
CC55 "GRM32ER61C476KE15L" 1210_270 10.75,7.5 r0 top value=47uF
CC56 "C0805C105K3RACTU" 0805_HV 10.5,5.9 r0 bottom value=1uF
CC57 "CL21A226KQQNNNE" 0805_HV 2.05,10.55 r90 bottom value=22uF
CC58 "GRM155R70J104KA01D" 0402 5.3,11.65 r90 bottom value=0.1uF
CC59 "C0402C103K4RACTU" 0402 9.3,10.6 r180 bottom value=0.01uF
CC60 "CL10B223KB8NNNC" FP-CL10B223KB8NNNC_0603-IPC_C 18.8,11.8 r90 top value=22nF
CC61 "GRM1885C1E821JA01D" 0603 20.35,12.1 r270 top value=820pF
CC62 "08053C224MAT2A" 0805_HV 17.95,12.1 r270 bottom value=0.22uF
CC63 "GCM155R71C104JA55D" 0402 15.7,41.7 r180 top value=0.1uF
CC64 "GCM155R71C104JA55D" 0402 33.95,41.7 r0 top value=0.1uF
CC65 "GCM155R71C104JA55D" 0402 14,34.2 r0 top value=0.1uF
CC66 "GCM155R71C104JA55D" 0402 35.6,34.2 r180 top value=0.1uF
CC67 "865081757008" FP-865081757008_SMT_CAP_10MM3_10MM3-MFG 7.35,63.6 r0 top value=47µF
CC68 "865081757008" FP-865081757008_SMT_CAP_10MM3_10MM3-MFG 7.35,52.9 r0 top value=47µF
D1 "BAS316,115" SOD-323 21.95,12.3 r90 top value=100V
DC1 "NRVB0540T1G" FP-NRVB0540T1G_SOD-123-MFG 20.35,26.95 r270 top
DC2 "STPS30M100DJF-TR" FP-STPS30M100DJF-TR_PowerFlat6-MFG 31.715,45.975 r180 bottom
DC3 "STPS30M100DJF-TR" FP-STPS30M100DJF-TR_PowerFlat6-MFG 11.865,38.125 r180 bottom
DC4 "STPS30M100DJF-TR" FP-STPS30M100DJF-TR_PowerFlat6-MFG 31.715,39.275 r180 bottom
DC5 "MMSZ4690-E3-08" SOD-123 8.4,24.55 r180 bottom value=5.6V
DC6 "MMSZ4690-E3-08" SOD-123 18.15,24.65 r0 bottom value=5.6V
DC7 "NRVB0540T1G" FP-NRVB0540T1G_SOD-123-MFG 22.4,26.95 r270 top
LC1 "TBD" WE-HCB_1890 29.8,59.6 r0 top
LOGO1 "CAUTION HOT SURFACE" IEC_HotSurface_Small 4.95,20.3 r180 bottom
Logo2 "Pb-Free Symbol" Pb-Free_Overlay_Medium 33.2,55.6 r180 bottom
Logo3 "WEEE logo" WEEE_Minimum 26.8,29.45 r180 bottom
Logo4 "FCC disclaimer" FCC_disclaimer 126.95,10.85 r90 bottom
QC1 "LMG3100R017" VBE0015A-MFG 5.9,45 r90 top
QC2 "LMG3100R017" VBE0015A-MFG 25.9,45 r90 top
QC3 "LMG3100R017" VBE0015A-MFG 5.9,37.6 r90 top
QC4 "LMG3100R017" VBE0015A-MFG 25.9,37.6 r90 top
QC5 "LMG3100R017" VBE0015A-MFG 14.9,45 r90 top
QC6 "LMG3100R017" VBE0015A-MFG 34.9,45 r90 top
QC7 "LMG3100R017" VBE0015A-MFG 14.9,37.6 r90 top
QC8 "LMG3100R017" VBE0015A-MFG 34.875,37.6 r90 top
R1 "CRCW04023R01FNED" FP-CRCW0402-e3-MFG 4.55,41.75 r180 top
R2 "CRCW04023R01FNED" FP-CRCW0402-e3-MFG 24.45,34.2 r0 top
R3 "CRCW12062R55FKEA" 1206 36.85,33.95 r0 bottom value=2.55
R4 "CRCW12062R55FKEA" 1206 17.4,33.9 r0 bottom value=2.55
R5 "CRCW0603681KFKEA" 0603 23.5,16.7 r90 top value=681k
R6 "CRCW060313K0FKEA" 0603 21.85,16.7 r270 top value=13.0k
R7 "CRCW04023R01FNED" FP-CRCW0402-e3-MFG 13.55,41.7 r180 top
R8 "CRCW04023R01FNED" FP-CRCW0402-e3-MFG 33.35,34.2 r0 top
RC1 "RC1206FR-073R3L" 1206 8.9,27 r180 bottom value=3.30
RC2 "RC1206FR-073R3L" 1206 18.2,27.05 r180 bottom value=3.30
RC3 "KRL2012E-M-R002-G-T5" 0508 18.3,61.4 r0 top value=0.002
RC4 "KRL2012E-M-R002-G-T5" 0508 18.3,64.4 r0 top value=0.002
RC5 "JR0805X35E" FP-JR0805X35E_0805-MFG 1.5,36.35 r270 bottom value=0
RC6 "JR0805X35E" FP-JR0805X35E_0805-MFG 23.55,12.65 r270 top value=0
RC7 "CRCW0603270KJNEA" 0603 2.95,15.45 r90 top value=270k
RC8 "RC0603FR-07100RL" 0603 5.45,26.25 r90 top value=100
RC9 "CRCW060310K0FKEA" 0603 12.85,13.2 r0 bottom value=10.0k
RC10 "RC0603FR-07100RL" 0603 7.15,26.25 r90 top value=100
RC11 "CRCW0603100RFKEA" 0603 12.3,12.1 r90 top value=100
RC12 "CRCW060310K7FKEA" 0603 9,12.1 r90 top value=10.7k
RC13 "CRCW06030000Z0EA" 0603 10.55,26.25 r90 top value=0
RC14 "CRCW06030000Z0EA" 0603 13.05,26.25 r90 top value=0
RC15 "CRCW040249K9FKED" 0402 11.4,8.65 r270 bottom value=49.9k
RC16 "CRCW06030000Z0EA" 0603 16.65,26.25 r90 top value=0
RC17 "RC0402FR-07220KL" 0402 10,8.65 r270 bottom value=220k
RC18 "JR0805X35E" FP-JR0805X35E_0805-MFG 15.9,12 r90 bottom value=0
RC19 "CRCW06030000Z0EA" 0603 14.6,26.25 r90 top value=0
RC20 "CRCW040230K0FKED" 0402 8.9,8.65 r90 bottom value=30.0k
RC21 "CRCW040230K0FKED" 0402 9.3,11.8 r0 bottom value=30.0k
RC22 "RK73H1ETTP2871F" FP-RK73H1ETTP2871F_0402-MFG 18.8,13.65 r90 top value=2.87k
RC23 "CRCW06038K25FKEA" 0603 13.95,12.1 r90 top value=8.25k
RC24 "CRCW0603100KFKEA" 0603 15.6,12.1 r90 top value=100k
RC25 "CRCW0603158KFKEA" 0603 17.25,12.1 r90 top value=158k
RC26 "RC1206FR-073R3L" 1206 8.9,29.6 r180 bottom value=3.30
RC27 "RC1206FR-073R3L" 1206 18.2,29.55 r180 bottom value=3.30
RC28 "KRL2012E-M-R002-G-T5" 0508 18.3,55.5 r0 top value=0.002
RC29 "KRL2012E-M-R002-G-T5" 0508 18.3,58.45 r0 top value=0.002
UC1 "LM5177DCPR" DCP0038A-MFG 13.975,18.95 r90 top
UC2 "TPSM863252RDX" RDX0007A-MFG 5.5,8.5 r90 bottom

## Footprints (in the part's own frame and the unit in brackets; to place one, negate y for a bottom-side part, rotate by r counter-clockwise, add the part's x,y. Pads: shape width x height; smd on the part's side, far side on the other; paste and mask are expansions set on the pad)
0402 [mm] "0402 from SM-752 data"
  rect 0.8x0.6 smd: 1(-0.6,0) 2(0.6,0)
  silkscreen extent -1.22,-0.52 1.22,0.52, body extent -0.55,-0.3 0.55,0.3, height 0.6
0508 [mm] "IPC nominal based on TDK C1220 type capacitors e4162_c.pdf"
  rect 0.8x2.25 smd: 1(-0.75,0) 2(0.75,0)
  silkscreen extent -1.44,-1.42 1.44,1.42, body extent -0.72,-1.1 0.72,1.1, height 1
0603 [mm] "0603 from SM-752 data"
  rect 1x0.95 smd: 1(-0.8,0) 2(0.8,0)
  silkscreen extent -1.52,-0.69 1.52,0.69, body extent -0.87,-0.47 0.87,0.47, height 1
0805_HV [mil] "0805 with 30mil clearance between pads"
  rect 50x63 smd: 1(-40,0) 2(40,0)
  silkscreen extent -74,-40 74,40, body extent -43,-29 43,29, height 57
1206 [mm] "1206 from SM-752 data"
  rect 1.3x1.85 smd: 1(-1.45,0) 2(1.45,0)
  silkscreen extent -2.4,-1.21 2.4,1.21, body extent -1.7,-0.9 1.7,0.9, height 1.35
1206_180 [mm] "1206_180"
  rect 1.1x1.6 smd: 1(-1.7,0) 2(1.7,0)
  silkscreen extent -0.9,-1 0.9,1, body extent -1.75,-0.95 1.75,0.95, height 1.8
1210_270 [mm] "1210"
  rect 1.3x2.7 smd: 1(-1.45,0) 2(1.45,0)
  silkscreen extent -2.32,-1.57 2.32,1.57, body extent -1.7,-1.35 1.7,1.35, height 2.7
DCP0038A-MFG [mm]
  rrect33% 1.5x0.3 smd paste+0 mask+0: 1(-2.9,4.5) 2(-2.9,4) 3(-2.9,3.5) 4(-2.9,3) 5(-2.9,2.5) 6(-2.9,2) 7(-2.9,1.5) 8(-2.9,1) 9(-2.9,0.5) 10(-2.9,0) 11(-2.9,-0.5) 12(-2.9,-1) 13(-2.9,-1.5) 14(-2.9,-2) 15(-2.9,-2.5) 16(-2.9,-3) 17(-2.9,-3.5) 18(-2.9,-4) 19(-2.9,-4.5) 20(2.9,-4.5) 21(2.9,-4) 22(2.9,-3.5) 23(2.9,-3) 24(2.9,-2.5) 25(2.9,-2) 26(2.9,-1.5) 27(2.9,-1) 28(2.9,-0.5) 29(2.9,0) 30(2.9,0.5) 31(2.9,1) 32(2.9,1.5) 33(2.9,2) 34(2.9,2.5) 35(2.9,3) 36(2.9,3.5) 37(2.9,4) 38(2.9,4.5)
  rrect3% 3.4x9.7 smd paste-1000 mask-1000: 39(0,0)
  silkscreen extent -4.35,-5.23 2.25,5.23, body extent -3.75,-5.15 3.75,5.15, height 0.25
FCC_disclaimer [mm]
FP-865081757008_SMT_CAP_10MM3_10MM3-MFG [mm]
  rrect5% 4.4x1.9 smd paste+0 mask+0: 1(-4.35,0) 2(4.35,0)
  silkscreen extent -7.23,-5.25 5.25,5.25, body extent -6.8,-5.5 6.8,5.5, height 0.25
FP-CL10B223KB8NNNC_0603-IPC_C [mm]
  rrect13% 0.758x0.812 smd paste+0 mask+0: 1(-0.627,0) 2(0.627,0)
  silkscreen extent -1.01,-0.85 1.01,0.85, body extent -1.11,-0.55 1.11,0.55, height 0.25
FP-CRCW0402-e3-MFG [mm]
  rect 0.6x0.6 smd paste+0 mask+0: 1(-0.525,0) 2(0.525,0)
  silkscreen extent -0.53,-0.7 0.53,0.7, body extent -0.92,-0.4 0.92,0.4, height 0.25
FP-JR0805X35E_0805-MFG [mm]
  rrect7% 1.4x1.44 smd paste+0 mask+0: 1(-1.1,0) 2(1.1,0)
  silkscreen extent 0,-0.72 0,0.72, body extent -1,-0.63 1,0.63, height 0.55
FP-NRVB0540T1G_SOD-123-MFG [mil]
  rrect11% 36x48 smd paste+0 mask+0: 1(-64.5,0) 2(64.5,0)
  silkscreen extent -110,-35 32,35, body extent -72,-31 72,31, height 53
FP-RK73H1ETTP2871F_0402-MFG [mm]
  rrect33% 0.4x0.3 smd paste+0 mask+0: 1(-0.45,0) 2(0.45,0)
  silkscreen extent -0.64,-0.53 0.64,0.53, body extent -0.75,-0.38 0.75,0.38, height 0.25
FP-STPS30M100DJF-TR_PowerFlat6-MFG [mm]
  rrect15% 0.65x1.25 smd paste-1000 mask+0: 1(-1.905,-2.725) 2(-0.635,-2.725) 3(0.635,-2.725) 4(1.905,-2.725)
  round 3.687 smd paste-1000 mask+0: 5(0.252,0.748)
  Top Layer region: -2.3,3.35 -1.575,3.35 -1.575,2.8 -0.95,2.8 -0.95,3.35 -0.312,3.35 -0.312,2.8 0.312,2.8 0.312,3.35 0.95,3.35 0.95,2.8 1.575,2.8 1.575,3.35 2.3,3.35 2.3,-1.3 -2.3,-1.3 -2.3,3.35
  silkscreen extent -3.36,-3.5 2.7,3.18, body extent -2.6,-3.08 2.6,3.07, height 1
IEC_HotSurface_Small [mm]
  silkscreen extent -2.72,-2.36 2.72,2.35
Pb-Free_Overlay_Medium [mm]
  silkscreen extent -2.41,-2.41 2.41,2.41
RDX0007A-MFG [mm]
  round 1.025 smd paste-1000 mask-1000: 1(-1.312,1.312)
  rrect13% 1.5x2.3 smd paste-1000 mask-1000: 2(-1.15,-0.675) 3(1.15,-0.675)
  round 0.991 smd paste-1000 mask-1000: 4(1.281,1.276)
  rrect45% 0.22x0.6 smd paste+0 mask-1000: 5(0.5,1.9) 6(0,1.9) 7(-0.5,1.9)
  Top Layer region: -1.9,1.8 -1.887,1.85 -1.85,1.887 -1.8,1.9 -1.8,1.9 -0.925,1.9 -0.887,1.892 -0.854,1.871 -0.833,1.838 -0.825,1.8 -0.825,1.8 -0.825,1.634 -0.818,1.596 -0.796,1.563 -0.796,1.563 -0.507,1.274 -0.474,1.252 -0.436,1.245 -0.436,1.245 -0.39,1.245 -0.34,1.232 -0.303,1.195 -0.29,1.145 -0.29,1.145 -0.29,0.825 -0.298,0.787 -0.319,0.754 -0.352,0.733 -0.39,0.725 -0.39,0.725 -1.8,0.725 -1.838,0.733 -1.871,0.754 -1.892,0.787 -1.9,0.825 -1.9,0.825
  Top Layer region: 1.9,1.8 1.892,1.838 1.871,1.871 1.838,1.892 1.8,1.9 1.8,1.9 0.925,1.9 0.887,1.892 0.854,1.871 0.833,1.838 0.825,1.8 0.825,1.8 0.825,1.634 0.818,1.596 0.796,1.563 0.796,1.563 0.507,1.274 0.474,1.252 0.436,1.245 0.436,1.245 0.39,1.245 0.352,1.237 0.319,1.216 0.298,1.183 0.29,1.145 0.29,1.145 0.29,0.825 0.298,0.787 0.319,0.754 0.352,0.733 0.39,0.725 0.39,0.725 1.8,0.725 1.838,0.733 1.871,0.754 1.892,0.787 1.9,0.825 1.9,0.825
  Keep-Out Layer region: -0.2,1.295 0.2,1.295 0.2,0.675 -0.2,0.675
  silkscreen extent -2.92,-2.17 2.07,2.68, body extent -1.65,-2 1.65,2, height 2.1
SOD-123 [mm] "On Semi recommended land pattern"
  rect 0.915x1.22 smd: 1(-1.637,0) 2(1.637,0)
  silkscreen extent -2.74,-1.17 2.03,1.17, body extent -1.93,-0.9 1.93,0.9, height 1.35
SOD-323 [mm] "NXP recommended land pattern"
  rect 0.6x0.6 smd paste-0.05: 1(-1.1,0) 2(1.1,0)
  silkscreen extent -2.06,-0.86 1.53,0.86, body extent -1.3,-0.67 1.3,0.68, height 1.1
VBE0015A-MFG [mm]
  round 0.265 smd paste+0 mask-1000: 1(-1.675,2.875) 11(1.675,2.875)
  rrect40% 0.7x0.25 smd paste+0 mask-1000: 2(-1.85,2.325) 3(-1.85,1.825) 4(-1.85,1.325) 5(-1.85,0.825) 8(1.85,1.325) 9(1.85,1.825) 10(1.85,2.325)
  rrect11% 1.9x3.95 smd paste-1000 mask-1000: 6(-1.3,-1.525) 7(1.3,-1.525)
  rrect40% 0.25x0.7 smd paste+0 mask-1000: 12(0.575,3.1) 13(0.075,3.1) 14(-0.425,3.1) 15(-0.925,3.1)
  Top Layer region: 2.15,2.7 2.169,2.704 2.185,2.715 2.196,2.731 2.2,2.75 2.2,2.75 2.2,2.9 2.193,2.925 2.175,2.943 2.15,2.95 2.15,2.95 1.85,2.95 1.812,2.958 1.779,2.979 1.758,3.012 1.75,3.05 1.75,3.05 1.75,3.4 1.746,3.419 1.735,3.435 1.719,3.446 1.7,3.45 1.7,3.45 1.55,3.45 1.531,3.446 1.515,3.435 1.504,3.419 1.5,3.4 1.5,3.4 1.5,2.75 1.504,2.731 1.515,2.715 1.531,2.704 1.55,2.7 1.55,2.7
  Top Layer region: -2.15,2.7 -2.169,2.704 -2.185,2.715 -2.196,2.731 -2.2,2.75 -2.2,2.75 -2.2,2.9 -2.193,2.925 -2.175,2.943 -2.15,2.95 -2.15,2.95 -1.85,2.95 -1.812,2.958 -1.779,2.979 -1.758,3.012 -1.75,3.05 -1.75,3.05 -1.75,3.4 -1.746,3.419 -1.735,3.435 -1.719,3.446 -1.7,3.45 -1.7,3.45 -1.55,3.45 -1.531,3.446 -1.515,3.435 -1.504,3.419 -1.5,3.4 -1.5,3.4 -1.5,2.75 -1.504,2.731 -1.515,2.715 -1.531,2.704 -1.55,2.7 -1.55,2.7
  silkscreen extent -2.92,-3.55 2.35,3.55, body extent -2.35,-3.6 2.35,3.55, height 0.25
WE-HCB_1890 [mm] "WURTH ELEKTRONIK"
  rect 6x12.45 smd: 1(-6.65,0) 2(6.65,0)
  silkscreen extent -9.7,-9.4 9.7,9.4, body extent -9.65,-9.35 9.65,9.35, height 9.2
WEEE_Minimum [mm] "WEEElie bin"
  silkscreen extent -2.42,-4.38 2.52,2.65

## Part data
C1 C2: library part CMP-0007473-4, "CAP, CERM, 1800 pF, 100 V, +/- 10%, X7R, 0603", Cap_Case=0603, Manufacturer=MuRata, Supplier Part Number 1=490-1477-1-ND, TempCo=X7R, Tolerance_%=10%, Value1=Unknown, Value2=100V, ValueDisplayed=1800pF
CC1 CC2 CC3 CC4 CC5 CC6 CC23 CC24 CC25 CC26 CC27 CC32 CC33 CC34 CC35 CC36 CC37 CC38 CC39 CC40 CC43 CC48: library part C3216X6S1H475K160AB, "CAP CER 4.7UF 100V X7S 1206", Cap_Case=1206, TempCo=X7S, Tolerance_%=10, Value2=100V, ValueDisplayed=4.7µF
CC7 CC8 CC9 CC10 CC11 CC12 CC13 CC14 CC15 CC16 CC17 CC18 CC19 CC20 CC21 CC22: "CAP, CERM, 0.022 µF, 100 V,+/- 10%, X7R, AEC-Q200 Grade 1, 0603", Cap_Case=0603, Manufacturer=TDK, Supplier Part Number 1=445-5814-1-ND, TempCo=X7R, Tolerance_%=10, Value1="0.083542 ohm", Value2=100V, ValueDisplayed=0.022µF
CC28 CC29 CC41 CC42 CC63 CC64 CC65 CC66: library part CMP-0080702-1, "CAP, CERM, 0.1 µF, 16 V,+/- 5%, X7R, AEC-Q200 Grade 1, 0402", Cap_Case=0402, Manufacturer=MuRata, Supplier Part Number 1=490-16433-1-ND, TempCo=X7R, Tolerance_%=5%, Value2=16V, ValueDisplayed=0.1µF
CC30 CC31 CC67 CC68: library part CMP-0095714-1, "Aluminum Electrolytic Capacitor 47uF 20% 80V 10.3x10.3x10.5mm SMT", Leakage Current=37.6uA, Manufacturer="Wurth Electronics", Operating Temperature Range="-55°C to +105°C", Tolerance_%=20%, ValueDisplayed=47uF
CC44: library part CMP-0078699-1, "CAP, CERM, 47 µF, 10 V,+/- 20%, X5R, 0805", Cap_Case=0805, Manufacturer=MuRata, Supplier Part Number 1=490-9961-1-ND, TempCo=X5R, Tolerance_%=20%, Value2=10V, ValueDisplayed=47µF
CC45: "CAP, CERM, 2.2 µF, 25 V,+/- 10%, X5R, 0805", Cap_Case=0805, Manufacturer=MuRata, Supplier Part Number 1=490-1701-1-ND, TempCo=X5R, Tolerance_%=10, Value1="0.006 ohm", Value2=25V, ValueDisplayed=2.2µF
CC46: "CAP, CERM, 220 pF, 50 V,+/- 10%, X7R, 0603", Cap_Case=0603, Manufacturer=MuRata, Supplier Part Number 1=490-1483-1-ND, TempCo=X7R, Tolerance_%=10, Value2=50V, ValueDisplayed=220pF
